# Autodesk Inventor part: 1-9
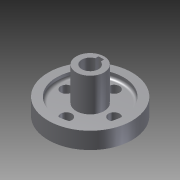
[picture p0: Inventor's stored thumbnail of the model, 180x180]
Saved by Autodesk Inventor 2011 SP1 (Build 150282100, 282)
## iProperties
Created: 2014-02
Part Number: 1-9
Document SubType Name: Modeling
Designer: Administrator
Density: 1 g/cm^3
Author: Administrator
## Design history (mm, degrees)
sketch "草图1"
  geometry: C1 r 15 at (0, 0); 1 further point
  constraints: 1 centre point, 1 coincident
  dimensions: "d0" = 30 diameter of C1
extrude "拉伸1" new body sketch "草图1" distance "d1" = 6; taper "d2" = 0 deg
sketch "草图2"
  geometry: C1 r 15 at (0, 0) reference; C2 r 12 at (0, 0)
  constraints: 1 centre point, 1 coincident
  dimensions: "d3" = 24 diameter of C2
extrude "拉伸2" cut sketch "草图2" distance "d4" = 2; taper "d5" = 0 deg
fillet "圆角1" dims "d6" = 1
sketch "草图3"
  geometry: C1 r 11 at (0, 0) reference; C2 r 5 at (0, 0)
  constraints: 1 centre point, 1 coincident
  dimensions: "d7" = 10 diameter of C2
extrude "拉伸3" join sketch "草图3" distance "d8" = 12; taper "d9" = 0 deg
sketch "草图4"
  geometry: L1 (-1, 4)-(1, 4); L2 (1, 4)-(1, 2.828); L3 (-1, 4)-(-1, 2.828); C1 r 5 at (0, 0) reference; A1 r 3 centre (0, 0) between (-1, 2.828) and (1, 2.828); 1 further point
  constraints: 6 end point, 2 point on circle, 1 centre point, 1 coincident, 1 horizontal, 1 midpoint, 1 parallel, 1 perpendicular, 1 vertical alignment
  dimensions: "d10" = 6 diameter of A1; "d11" = 2 distance of L1.start L1.end
extrude "拉伸4" cut sketch "草图4" stored distance "d12" = 12; taper "d13" = 0 deg
sketch "草图5"
  geometry: C1 r 2 at (-8.544, 0)
  constraints: 1 centre point
  dimensions: "d14" = 4 diameter of C1
extrude "拉伸5" cut sketch "草图5" stored distance "d15" = 12; taper "d16" = 0 deg
pattern_circular "环形阵列1" dims angle "d18" = 360 deg
node "实体1"
